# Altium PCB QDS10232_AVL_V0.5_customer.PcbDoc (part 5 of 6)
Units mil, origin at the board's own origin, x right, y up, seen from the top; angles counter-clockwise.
Board outline 3500 x 3799 mil, 6 copper layers (Top Layer, GND, INT1, PWR1, PWR2, Bottom Layer), stack 78.834 mil thick; 254 components, 204 nets, 7039 pads, 595 vias.
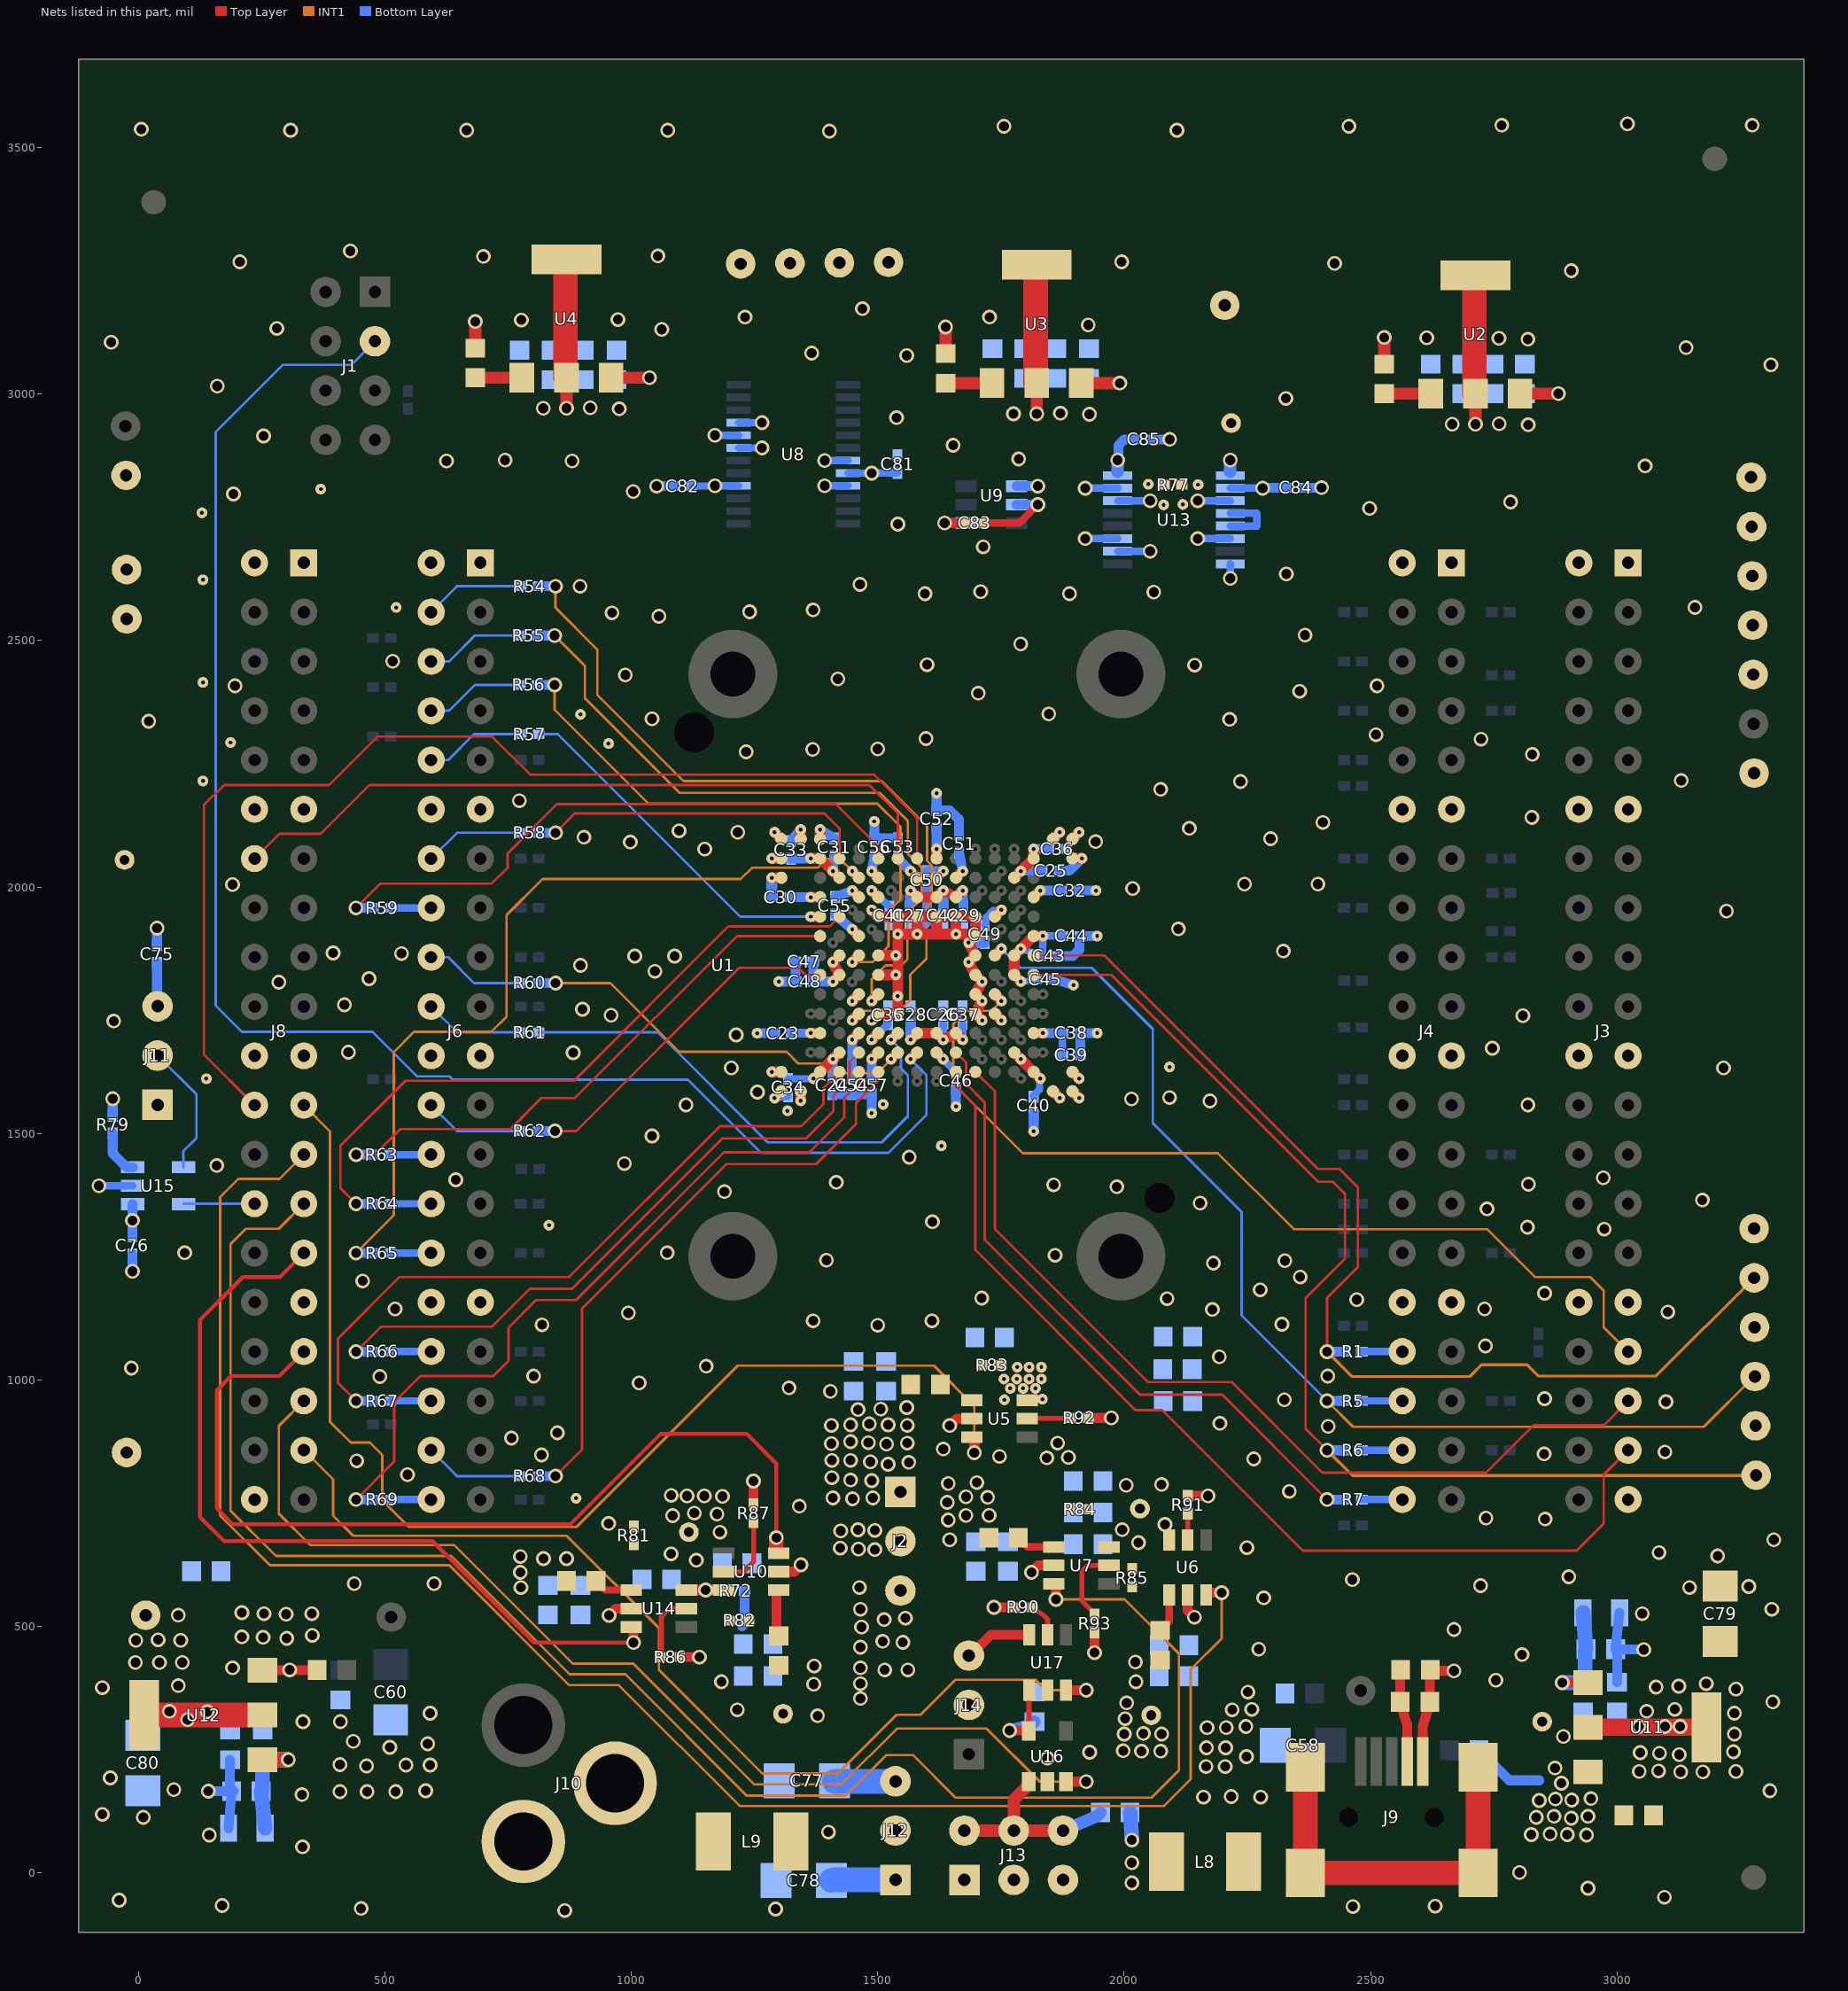
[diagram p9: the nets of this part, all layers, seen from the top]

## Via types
v1: diameter 30, hole 20, Top Layer to Bottom Layer, 595 vias

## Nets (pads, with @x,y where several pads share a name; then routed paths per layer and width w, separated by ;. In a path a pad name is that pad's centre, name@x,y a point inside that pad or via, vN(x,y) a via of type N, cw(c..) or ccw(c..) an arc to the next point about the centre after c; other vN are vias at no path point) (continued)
DQ16: pad.@1448.34,1729.46 R54.2 U1.E5 | length 1597.2
  Top Layer w22: pad.@1448.34,1729.46 U1.E5@1461.91,1743.02
  INT1 w5: v1(846.4,2610) 846.4,2566.6 931,2482 931,2390 1106,2215 1508,2215 1600,2123 1600,2053 1609,2044 1609,1969 1599,1959 1599,1855 1566,1822 1566,1770 1545,1749 1467.88,1749 pad.@1448.34,1729.46
  Bottom Layer w20: R54.2@812,2610 v1(846.4,2610)
DQ16_1: J6.4 R54.1 | length 203.8
  Bottom Layer w5: J6.4@593.96,2557.56 646.4,2610 R54.1@776,2610
DQ17: pad.@1487.71,1768.83 R55.2 U1.F6 | length 1401.7
  Top Layer w22: pad.@1487.71,1768.83 U1.F6@1501.28,1782.39
  INT1 w5: v1(844.4,2510) 906,2448.4 906,2383 1098,2191 1504,2191 1561,2134 1561,2068 1589,2040 1589,1977 1560,1948 1560,1853 1548,1841 1516,1841 1487.71,1812.71 pad.@1487.71,1768.83
  Bottom Layer w20: R55.2@810,2510 v1(844.4,2510)
DQ17_1: J6.6 R55.1 | length 203.8
  Bottom Layer w5: J6.6@593.96,2457.56 630.36,2457.56 682.8,2510 R55.1@776,2510
DQ18: pad.@1448.34,1847.57 R56.2 U1.E8 | length 1243.1
  Top Layer w22: pad.@1448.34,1847.57 U1.E8@1461.91,1861.13
  INT1 w5: v1(844.4,2410) 844.4,2359.52 1034.92,2169 1499,2169 1546,2122 1546,1975 1522,1951 1522,1880 1489.57,1847.57 pad.@1448.34,1847.57
  Bottom Layer w20: R56.2@810,2410 v1(844.4,2410)
DQ18_1: J6.8 R56.1 | length 203.8
  Bottom Layer w5: J6.8@593.96,2357.56 630.36,2357.56 682.8,2410 R56.1@776,2410
DQ19: pad.@1363.98,1939.87 R57.2 U1.C10 | length 724.5
  Top Layer w22: pad.@1363.98,1939.87 U1.C10@1383.17,1939.87
  Bottom Layer w5: R57.2@812,2310 851,2310 1221.13,1939.87 pad.@1363.98,1939.87
DQ19_1: J6.10 R57.1 | length 203.8
  Bottom Layer w5: J6.10@593.96,2257.56 628.56,2257.56 681,2310 R57.1@776,2310
DQ20: R58.2 U1.D13 | length 699.8
  Top Layer w5: v1(846.4,2110) 885.4,2149 1392,2149 1422.54,2118.46 U1.D13@1422.54,2057.98
  Bottom Layer w20: R58.2@812,2110 v1(846.4,2110)
DQ20_1: J6.14 R58.1 | length 203.8
  Bottom Layer w5: J6.14@593.96,2057.56 646.4,2110 R58.1@776,2110
DQ21: R59.2 U1.F13 | length 1257.7
  Top Layer w5: v1(441.56,1957.56) 491,2007 717,2007 749,2039 749,2068 849,2168 1415,2168 1501.28,2081.72 U1.F13@1501.28,2057.98
  Bottom Layer w20: v1(441.56,1957.56) R59.2@475.96,1957.56
DQ21_1: J6.16 R59.1 | length 82
  Bottom Layer w15: R59.1@511.96,1957.56 J6.16@593.96,1957.56
DQ22: pad.@1527.08,1650.72 R60.2 U1.G3 | length 822
  Top Layer w22: pad.@1527.08,1650.72 U1.G3@1540.65,1664.28
  INT1 w5: v1(846.4,1805.12) 957.88,1805.12 1097,1666 1315,1666 1339,1642 1386,1642 1406,1622 1498.36,1622 pad.@1527.08,1650.72
  Bottom Layer w20: R60.2@812,1805.12 v1(846.4,1805.12)
DQ22_1: J6.18 R60.1 | length 203.8
  Bottom Layer w5: J6.18@593.96,1857.56 628.44,1857.56 680.88,1805.12 R60.1@776,1805.12
DQ23: pad.@1527.08,1690.09 R61.2 U1.G4 | length 1051.7
  Top Layer w22: pad.@1527.08,1690.09 U1.G4@1540.65,1703.65
  Bottom Layer w5: R61.2@812,1705.12 1053.88,1705.12 1277,1482 1508,1482 1561,1535 1561,1618 1547,1632 1547,1670.16 pad.@1527.08,1690.09
DQ23_1: J6.20 R61.1 | length 203.8
  Bottom Layer w5: J6.20@593.96,1757.56 646.4,1705.12 R61.1@776,1705.12
DQ24: R62.2 U1.C7 | length 715.2
  Top Layer w5: v1(845.36,1505.12) 888.12,1505.12 1219,1836 1338.53,1836 1352.76,1821.76 U1.C7@1383.17,1821.76
  Bottom Layer w20: R62.2@810.96,1505.12 R62.2@812,1505.12 v1(845.36,1505.12)
DQ24_1: J6.24 R62.1 | length 203.8
  Bottom Layer w5: J6.24@593.96,1557.56 646.4,1505.12 R62.1@776,1505.12
DQ25: R63.2 U1.C9 | length 1159.3
  Top Layer w5: v1(442,1457) 479.36,1457 531.36,1509 755,1509 818,1572 886,1572 1214.5,1900.5 U1.C9@1383.17,1900.5
  Bottom Layer w20: v1(442,1457) R63.2@475.36,1457 R63.2@476.4,1457
DQ25_1: J6.26 R63.1 | length 82
  Bottom Layer w15: R63.1@511.36,1457 J6.26@593.36,1457
DQ26: R64.2 U1.D10 | length 1370
  Top Layer w5: v1(441.56,1357.56) 410,1389.12 410,1475 542,1607 884,1607 1197,1920 1402.66,1920 U1.D10@1422.54,1939.87
  Bottom Layer w20: v1(441.56,1357.56) R64.2@475.96,1357.56
DQ26_1: J6.28 R64.1 | length 82
  Bottom Layer w15: R64.1@511.96,1357.56 J6.28@593.96,1357.56
DQ27: pad.@1448.34,2032.18 R65.2 U1.E12 | length 1716.4
  Top Layer w22: pad.@1448.34,2032.18 U1.E12@1461.91,2018.61
  INT1 w5: v1(441.56,1257.56) 518,1334 518,1665 559,1706 716,1706 747,1737 747,1943 820,2016 1222,2016 1245,2039 1378,2039 1396,2057 1423.52,2057 pad.@1448.34,2032.18
  Bottom Layer w20: v1(441.56,1257.56) R65.2@475.96,1257.56
DQ27_1: J6.30 R65.1 | length 82
  Bottom Layer w15: R65.1@511.96,1257.56 J6.30@593.96,1257.56
DQ28: R66.2 U1.E3 | length 1345.5
  Top Layer w5: v1(441.56,1057.56) 492,1108 717,1108 794,1185 880,1185 1185,1490 1355,1490 1410,1545 1410,1576 1443,1609 1443,1645.38 U1.E3@1461.91,1664.28
  Bottom Layer w20: v1(441.56,1057.56) R66.2@475.96,1057.56
DQ28_1: J6.34 R66.1 | length 82
  Bottom Layer w15: R66.1@511.96,1057.56 J6.34@593.96,1057.56
DQ29: R67.2 U1.D2 | length 1436.5
  Top Layer w5: v1(441.56,957.56) 405,994.12 405,1084 530,1209 874,1209 1180,1515 1345,1515 1390,1560 1390,1592.38 U1.D2@1422.54,1624.91
  Bottom Layer w20: v1(441.56,957.56) R67.2@475.96,957.56
DQ29_1: J6.36 R67.1 | length 82
  Bottom Layer w15: R67.1@511.96,957.56 J6.36@593.96,957.56
DQ30: R68.2 U1.F2 | length 1232.1
  Top Layer w5: v1(846.4,805.12) 900,858.72 900,1145 1193,1438 1375,1438 1456,1519 1456,1562 1501.28,1607.28 U1.F2@1501.28,1624.91
  Bottom Layer w20: R68.2@812,805.12 v1(846.4,805.12)
DQ30_1: J6.38 R68.1 | length 203.8
  Bottom Layer w5: J6.38@593.96,857.56 646.4,805.12 R68.1@776,805.12
DQ31: R69.2 U1.E2 | length 1559.9
  Top Layer w5: v1(441.56,757.56) 519,835 519,955 572,1008 720,1008 751,1039 751,1106 807,1162 888,1162 1188,1462 1361,1462 1432,1533 1432,1572 1461.91,1601.91 U1.E2@1461.91,1624.91
  Bottom Layer w20: v1(441.56,757.56) R69.2@475.96,757.56
DQ31_1: J6.40 R69.1 | length 82
  Bottom Layer w15: R69.1@511.96,757.56 J6.40@593.96,757.56
E1: J8.28 U15.5 | length 144.5
  Bottom Layer w5: U15.5@91.57,1356.6 92.54,1357.56 J8.28@235.69,1357.56
E#: E#.1 R1.2 U1.P8 | length 2235.4
  Top Layer w5: U1.P8@1816.24,1861.13 1959.87,1861.13 2393,1428 2437,1428 2474,1391 2474,1229 2411.64,1166.64 v1(2411.64,1057.56)
  INT1 w6: v1(2411.64,1057.56) 2462.2,1007 2701,1007 2725,1031 2817,1031 2840,1008 3079,1008 E#.1@3278,1207
  Bottom Layer w20: v1(2411.64,1057.56) R1.2@2446.04,1057.56
E#_1: J4.34 R1.1 | length 82
  Bottom Layer w15: R1.1@2482.04,1057.56 J4.34@2564.04,1057.56
EXT_VCCE_EN: J8.25 U6.3 | length 3523.1
  Top Layer w20: U6.3@2166,568.64 v1(2197.6,568.64)
  INT1 w5: J8.25@335.69,1457.56 286.13,1408 203,1408 166,1371 166,725 267,624 631,624 874,381 975,381 1220,136 2081,136 2135,190 2135,413 2197.6,475.6 v1(2197.6,568.64)
G#: G#.1 R6.2 U1.P7 | length 2307.8
  Top Layer w5: U1.P7@1816.24,1821.76 1974.24,1821.76 2394,1402 2423,1402 2448,1377 2448,1246 2368,1166 2368,901.2 v1(2411.64,857.56)
  INT1 w6: v1(2411.64,857.56) 2463.2,806 G#.1@3277,806
  Bottom Layer w20: v1(2411.64,857.56) R6.2@2446.04,857.56
G#_1: J4.38 R6.1 | length 82
  Bottom Layer w15: R6.1@2482.04,857.56 J4.38@2564.04,857.56
GND: C1.2 C2.2 C3.2 C4.2 C5.2 C6.2 C7.2 C8.2 C9.2 C10.2 C11.2 C12.2 C13.2 C14.2 C15.2 C16.2 C17.2 C18.2 C19.2 C20.2 C21.2 C22.2 C23.2 C24.2 C25.2 C26.2 C27.2 C28.2 C29.2 C30.2 C31.2 C32.2 C33.2 C34.2 C35.2 C36.2 C37.2 C38.2 C39.2 C40.2 C41.2 C42.2 C43.2 C44.2 C45.2 C46.2 C47.2 C48.2 C49.2 C50.2 C51.2 C52.2 C53.2 C54.2 C55.2 C56.2 C57.2 C58.2 C59.2 C62.2 C63.2 C64.2 C65.2 C66.2 C67.2 C68.2 C69.2 C70.2 C71.2 C72.2 C73.2 C74.2 C75.1 C76.1 C77.2 C78.2 C79.2 C80.2 C81.2 C82.2 C83.2 C84.2 C85.2 C86.2 C87.2 GND1.1 GND2.1 GND3.1 GND4.1 GND5.1 GND6.1 GND7.1 GND8.1 GND9.1 GND10.1 GND11.1 GND12.1 GND13.1 GND14.1 J3.11 J3.12 J3.21 J3.22 J3.31 J3.32 J3.39 J4.11 J4.12 J4.21 J4.22 J4.31 J4.32 J6.11 J6.12 J6.21 J6.22 J6.31 J6.32 J8.11 J8.12 J8.21 J8.22 J8.31 J9.5 J11.1 L8.1 L9.1 pad.@129,2759 pad.@131,2215 pad.@131,2415 pad.@131,2623 pad.@138,1611 pad.@187,2293 pad.@370,2807 pad.@523,2567 pad.@833,1314 pad.@888,760 pad.@897,2350 pad.@954,2291 pad.@1255.3,1703.45 pad.@1285.24,1624.91 pad.@1285.24,2018.61 pad.@1285.24,2057.98 pad.@1290.86,1571.98 pad.@1290.86,2110.92 pad.@1299.19,1808.2 pad.@1317,1546 pad.@1343.8,2116.54 pad.@1343.79,1566.36 pad.@1383.17,2116.54 pad.@1448.34,1768.83 pad.@1448.34,1914.07 pad.@1487.71,1540.94 pad.@1487.71,1729.46 pad.@1487.71,1953.44 pad.@1492.98,2133.05 pad.@1511,1559 pad.@1536.7,1821.76 pad.@1536.7,1861.13 pad.@1540.65,1778.45 pad.@1540.65,1904.45 pad.@1580.02,1904.45 pad.@1619.39,2190.09 pad.@1629,1475 pad.@1658.76,1554.51 pad.@1658.76,1904.45 pad.@1684.56,1847.57 pad.@1684.56,1886.94 pad.@1711.69,1729.46 pad.@1711.69,1768.83 pad.@1711.69,1808.2 pad.@1816.24,1504.36 pad.@1869.17,1571.98 pad.@1869.17,2110.92 pad.@1897,1801 pad.@1908.54,1571.98 pad.@1908.54,1611.35 pad.@1908.54,2110.92 pad.@1914.16,2057.98 pad.@1942.73,1992.81 pad.@1945.2,1703.65 pad.@1945.2,1900.5 pad.@2092,1635 R2.2 R3.2 R4.2 R71.2 R72.2 R74.2 R75.2 R78.1 R86.2 R87.2 R90.2 R91.2 R92.2 R93.2 U1.A1 U1.A2 U1.A12 U1.A13 U1.A14 U1.B1 U1.B14 U1.C14 U1.E6 U1.E9 U1.F5 U1.F7 U1.F8 U1.F10 U1.G5 U1.G10 U1.H10 U1.J10 U1.K10 U1.L5 U1.L6 U1.L7 U1.L8 U1.L9 U1.L10 U1.R1 U1.R14 U1.T1 U1.T2 U1.T13 U1.T14 U2.3 U3.3 U4.3 U5.2 U6.2 U7.2 U8.7 U8.8 U8.9 U8.19 U9.1 U9.2 U10.2 U13.6 U13.8 U13.11 U14.2 U15.2 U16.2 U17.2 | length 4934.4
  Top Layer w15: C83.2@1715,2738 1787.18,2738 v1(1824.78,2775.6)
  Top Layer w20: v1(954.82,522.4) 968.82,536.4 U14.2@1004.64,536.4 ; R86.2@1096.9,438 v1(1138.1,438) ; R87.2@1248,753.9 v1(1248,795.1) ; U10.2@1294.45,611.2 1330.27,611.2 v1(1344.27,625.2) ; v1(1646.13,907.6) 1660.13,921.6 U5.2@1695.94,921.6 ; v1(1735.9,539) R90.2@1777.1,539 ; v1(1812,610) 1826,624 U7.2@1861.82,624 ; R92.2@1932.9,923 v1(1974.1,923) ; v1(1940,446.9) R93.2@1940,488.1 ; U6.2@2128.6,568.64 2128.6,532.82 v1(2142.6,518.82) ; R91.2@2128.9,765 v1(2170.1,765) ; J9.5@2605.61,226.39 2605.61,296.61 C62.2@2620,347 R78.1@2620,411 ; R78.1@2621,410 v1(2669,410)
  Top Layer w22: pad.@1285.24,1624.91 U1.A2@1304.42,1624.91 ; pad.@1285.24,2018.61 U1.A12@1304.42,2018.61 ; pad.@1285.24,2057.98 U1.A13@1304.42,2057.98 ; pad.@1290.86,1571.98 U1.A1@1304.42,1585.54 ; pad.@1290.86,2110.92 U1.A14@1304.42,2097.35 ; pad.@1343.79,1566.36 U1.B1@1343.8,1585.54 ; U1.B14@1343.8,2097.35 pad.@1343.8,2116.54 ; U1.C14@1383.17,2097.35 pad.@1383.17,2116.54 ; pad.@1448.34,1768.83 U1.E6@1461.91,1782.39 ; pad.@1448.34,1914.07 U1.E9@1461.91,1900.5 ; pad.@1487.71,1729.46 U1.F5@1501.28,1743.02 U1.G5@1540.65,1743.02 pad.@1540.65,1778.45 pad.@1540.65,1813.87 ; pad.@1487.71,1953.44 U1.F10@1501.28,1939.87 U1.G10@1540.65,1939.87 ; U1.F7@1501.28,1821.76 pad.@1536.7,1821.76 ; U1.F8@1501.28,1861.13 pad.@1536.7,1861.13 ; 1540.65,1798.17 1540.65,1833.6 1540.65,1869.02 pad.@1540.65,1904.45 ; 1619.39,1904.45 U1.J10@1619.39,1939.87 ; pad.@1650.87,1904.45 1615.44,1904.45 pad.@1580.02,1904.45 ; U1.L9@1694.18,1904.45 pad.@1658.76,1904.45 U1.K10@1658.76,1939.87 ; pad.@1711.69,1729.46 U1.L5@1698.13,1743.02 pad.@1711.69,1768.83 U1.L6@1698.13,1782.39 pad.@1711.69,1808.2 U1.L7@1698.13,1821.76 pad.@1684.56,1847.57 U1.L8@1698.13,1861.13 pad.@1684.56,1886.94 U1.L9@1698.13,1900.5 U1.L10@1698.13,1939.87 U1.K10@1658.76,1939.87 ; U1.R1@1855.61,1585.54 pad.@1869.17,1571.98 ; U1.R14@1855.61,2097.35 pad.@1869.17,2110.92 ; U1.T1@1894.98,1585.54 pad.@1908.54,1571.98 ; U1.T2@1894.98,1624.91 pad.@1908.54,1611.35 ; U1.T13@1894.98,2057.98 pad.@1914.16,2057.98 ; U1.T14@1894.98,2097.35 pad.@1908.54,2110.92 ; pad.@1540.65,1904.45 pad.@1580.02,1904.45 ; pad.@1540.65,1904.45 U1.G10@1540.65,1939.87 ; U1.G10@1540.65,1939.87 U1.H10@1580.02,1939.87 ; pad.@1580.02,1904.45 U1.H10@1580.02,1939.87 ; U1.H10@1580.02,1939.87 U1.J10@1619.39,1939.87 ; U1.J10@1619.39,1939.87 U1.K10@1658.76,1939.87
  Top Layer w25: R4.2@683.7,3093 v1(683.7,3146.93) ; U4.3@959.07,3033 v1(1037,3033) ; R3.2@1637.7,3082 v1(1637.7,3135.93) ; U3.3@1913.07,3022 v1(1991,3022) ; R2.2@2527.7,3060.71 v1(2527.7,3114.64) ; U2.3@2803.07,3000.71 v1(2881,3000.71)
  Bottom Layer w15: v1(-80,1394) U15.2@-11.57,1394 ; v1(1169.84,2916.13) U8.8@1217.56,2916.13 ; U8.7@1217.56,2890.54 v1(1265.28,2890.54) ; U8.9@1217.56,2941.72 v1(1265.28,2941.72) ; pad.@1290.86,1571.98 C34.2@1318,1575 ; v1(1392.28,2864.95) U8.19@1440,2864.95 ; v1(1921,2706.61) U13.11@1986.83,2706.61 ; v1(2149.35,2706.61) U13.6@2215.17,2706.61 ; v1(2215.17,2626) U13.8@2215.17,2655.43
  Bottom Layer w20: v1(-12,1220.6) C76.1@-12,1255 ; C75.1@38,1882 v1(38,1916.4) ; v1(141.9,166) R75.2@183.1,166 ; C74.2@183,91 R75.2@189,166 ; C73.2@186,230 186,174 R75.2@194,166 ; v1(1051.6,2813) C82.2@1086,2813 ; 1224.78,500.4 1229.82,505.44 R72.2@1229.82,572.4 ; pad.@1255.3,1703.45 C23.2@1289.7,1703.45 ; pad.@1299.19,1808.2 C48.2@1333.59,1808.2 1333.59,1849 C47.2@1333,1849 ; C33.2@1324,2093 pad.@1343.8,2116.54 ; pad.@1383.17,2116.54 C31.2@1411.7,2098.45 ; C24.2@1407.71,1580 C54.2@1447.71,1580 C57.2@1487.71,1580 ; C55.2@1413,1943.99 pad.@1448.34,1914.07 ; pad.@1487.71,1540.94 C57.2@1487.71,1575.34 ; pad.@1492.98,2133.05 C56.2@1492.98,2098.65 1540.31,2098.65 C53.2@1540.65,2098.98 ; 1597,1926 1600,1929 C50.2@1600,1996 ; pad.@1619.39,2190.09 C52.2@1619.39,2155.69 1646.31,2155.69 1665,2137 C51.2@1665,2106 ; pad.@1658.76,1554.51 C46.2@1658.76,1588.91 ; pad.@1685,1886 C49.2@1717,1886 ; U9.2@1781.36,2775.6 v1(1824.78,2775.6) ; U9.1@1781.36,2813 v1(1824.78,2813) ; pad.@1816.24,1504.36 C40.2@1816.24,1538.76 ; C45.2@1858,1813 pad.@1897,1801 ; C43.2@1866,1860 1896,1860 1909,1873 1909,1898.7 C44.2@1910.8,1900.5 pad.@1945.2,1900.5 ; C25.2@1869,2033 1889.18,2033 pad.@1914.16,2057.98 ; C32.2@1908.32,1992.81 pad.@1942.73,1992.81 ; C38.2@1910.8,1703.65 C38.2@1911,1703.65 ; C39.2@1911,1659 C38.2@1911,1703.65 ; pad.@1945.2,1703.65 C38.2@1911,1703.65 ; C85.2@2058,2908 v1(2092.4,2908) ; C84.2@2366,2810 v1(2400.4,2810) ; C71.2@3000,387 R74.2@3000,451 ; C72.2@3005,528 R74.2@2997,454 R74.2@3000,451 ; v1(3054,453) 3053.5,453.5 3002.5,453.5 R74.2@3000,451
  Bottom Layer w22: C30.2@1285.24,1981.76 pad.@1285.24,2018.61
  Bottom Layer w30: C87.2@2012,123 v1(2015.55,66.8)
  other v1: 865,-76 1293,-73 452,-72 2464,-68 2631,-67 170,-66 -39,-55 3096,-49 2941,-31 2015.55,-20.2 2802,1 2015.55,20.8 333,53 144,77 1400,83 10,113 -73,119 2161,154 2277,154 2217,155 332,159 3310,167 72,169 -57,193 2166,216 2205,216 1844,233 2248,236 1930,245 2167,254 2206,254 2168,295 2207,295 2247,297 334,307 1215,331 2219,331 2259,332 3316,347 2251,367 -73,376 1183,388 2754,391 2807,443 2273,454 2669,494 3051,526 3314,535 2283,558 3147,579 3267,581 2723,583 438,587 600,587 2463,595 2902,601 3204,643 3085,650 2249,660 3318,676 954,709 2854,718 2734,720 1341,744 2335,774 546,808 443,836 2263,840 1843,842 1887,843 1747,845 818,848 2852,850 3097,854 1633,860 1865,872 757,882 850,893 2414,906 2194,912 3099,956 2325,960 2853,962 1320,984 1016,994 490,1007 802,1008 2413,1008 -14,1024 1152,1028 2193,1047 2733,1069 1500,1111 819,1112 2320,1113 1369,1120 1610,1120 994,1136 3103,1138 2179,1143 521,1144 2731,1144 2472,1163 2087,1165 1711,1166 2853,1176 2276,1183 455,1201 2357,1209 2181,1237 2326,1242 1396,1243 1860,1253 94,1258 1073,1258 2974,1306 2818,1310 1611,1321 2736,1347 2154,1359 3173,1365 1189,1382 1985,1392 1857,1396 2820,1397 1416,1401 644,1406 2972,1410 159,1435 986,1439 1564,1452 1042,1495 1111,1558 2819,1558 2174,1566 2015,1570 2092,1573 1256,1584 1203,1633 3216,1633 882,1664 426,1665 2747,1673 1213,1700 -50,1728 2809,1739 959,1740 901,1752 418,1761 285,1807 468,1814 1048,1829 897,1841 1007,1860 1088,1860 534,1865 395,1866 2323,1870 2110,1915 3222,1951 2017,1997 191,2005 2244,2006 2393,2006 1149,2077 998,2091 1942,2092 2297,2098 904,2101 1216,2111 1097,2114 2132,2119 2403,2131 2827,2141 773,2175 2074,2198 2236,2214 3130,2216 2828,2269 1233,2274 1368,2279 1500,2280 2724,2300 1598,2301 2511,2309 21,2336 2214,2340 1042,2341 1847,2351 1704,2393 2356,2397 196,2408 2513,2408 1419,2422 988,2430 2143,2450 1600,2451 516,2458 1790,2493 2367,2511 1056,2549 961,2556 1240,2558 1369,2562 3158,2567 1596,2595 1889,2595 2060,2598 1709,2599 896,2610 1464,2614 2329,2635 1714,2690 1541,2736 2498,2768 2784,2781 193,2797 1004,2802 3057,2854 625,2864 880,2864 744,2866 1786,2868 1653,2896 254,2915 1538,2952 2328,2991 160,3016 3312,3059 1559,3078 1366,3083 3140,3094 -55,3105 2819,3111 2760.18,3113 2614,3114 1062,3131 281,3133 1927,3140 777,3150 973,3151 1231,3156 1727,3156 1469,3173 2907,3250 2427,3265 206,3268 1995,3268 700,3279 1054,3280 430,3290 1402,3533 309,3535 666,3535 1074,3535 2107,3535 6,3537 1756,3543 2456,3543 2766,3545 3274,3545 3021,3548
GND_EXT: C60.2 C61.2 J10.GND J10.GNDBREAK L9.2
  other v1: 409,165 464,165 522,165 583,167 463,217 543,219 592,219 409,220 510,255 587,262 436,267 410,307 592,324
INT#: J8.14 U1.G13 | length 1482.1
  Top Layer w5: J8.14@235.69,2057.56 286.13,2108 370,2108 469,2207 1483,2207 1540.65,2149.35 U1.G13@1540.65,2057.98
INT_VCCE_EN: J8.23 U5.3 | length 2409.2
  Top Layer w20: v1(1695.94,852.6) U5.3@1695.94,884.2
  INT1 w5: J8.23@335.69,1557.56 389,1504.25 389,915 431,873 470,873 495,848 495,756 549,702 889,702 1216,1029 1614,1029 1695.94,947.06 v1(1695.94,852.6)
NetC62_1: C62.1 J9.4 R78.2 | length 188.1
  Top Layer w20: R78.2@2561,412 2560,411 C62.1@2560,347 2574.11,300.89 J9.4@2574.11,226.39
NetC72_1: C72.1 R73.2 R74.1 U11.1 | length 237.1
  Top Layer w20: v1(2888.9,386.1) U11.1@2941,386.1
  Bottom Layer w20: R74.1@2937,454 R74.1@2941,450
  Bottom Layer w30: v1(2888.9,386.1) R73.2@2930.1,386.1 ; C72.1@2931,528 R74.1@2937,454 ; R73.2@2935,386.1 R74.1@2935,450
NetC74_1: C74.1 R75.1 R76.2 U12.1 | length 233.9
  Top Layer w30: U12.1@252,229.9 v1(304.1,229.9)
  Bottom Layer w20: R75.1@249,166 R75.1@252,169
  Bottom Layer w30: R75.1@249,166 C74.1@257,91 ; R75.1@252,169 R76.2@252,229.9 ; R76.2@262.9,229.9 v1(304.1,229.9)
NetC86_1: C86.1 U16.5 U17.1 | length 178.9
  Top Layer w10: U16.5@1806.6,288 1806.9,288.3 1806.9,289 1806.9,370.7 U17.1@1807.2,371
  Top Layer w20: v1(1767.5,289) 1806.9,289 U16.5@1808.7,289
  Bottom Layer w25: v1(1767.5,289) 1810.5,300.5 C86.1@1818,307
NetC87_1: C87.1 J13.4 J13.5 J13.6 U16.1 | length 399.4
  Top Layer w25: J13.4@1676,86 J13.5@1776,86 ; U16.1@1805.1,183.71 U16.1@1806.6,185.21 1806.6,179.71 1776,149.11 J13.5@1776,86 ; J13.6@1876,86 J13.5@1776,86
  Bottom Layer w25: J13.6@1876,86 1945.5,115.5 C87.1@1952,123
NetJ9_6: J9.6 J9.7 J9.8 J9.9 L8.2 | length 799.9
  Top Layer w50: J9.8@2353.05,17 J9.8@2367.42,2.63 ; J9.6@2367.42,214.57 2367.42,133 J9.8@2367.42,2.63 ; J9.7@2717.81,214.57 J9.9@2717.81,0.01 J9.8@2367.42,0.01 J9.8@2367.42,2.63
NetJ11_2: J11.2 U15.4 | length 270.3
  Bottom Layer w5: J11.2@39,1658 118,1579 118,1491 91.57,1464.57 U15.4@91.57,1431.4
NetJ14_3: J14.3 U17.6 | length 139.6
  Top Layer w20: J14.3@1685,441 1687.27,441 1729.27,483 U17.6@1807.2,483
NetL1_2: L1.2 R83.2 U5.1
NetL2_1: L2.1 R85.1 U6.1 | length 84.2
  Top Layer w15: L2.1@2073,492 2091.2,510.2 U6.1@2091.2,568.64
NetL3_2: L3.2 R84.2 U7.1 | length 83.9
  Top Layer w15: L3.2@1785.59,680 1804.19,661.4 U7.1@1861.82,661.4
NetL4_2: L4.2 R81.2 U14.1 | length 83.9
  Top Layer w15: L4.2@928.41,592.4 947.01,573.8 U14.1@1004.64,573.8
NetL5_1: L5.1 R82.1 U10.1 | length 74.6
  Top Layer w15: L5.1@1294.45,499.77 L5.1@1294.82,499.4
  Top Layer w20: L5.1@1294.45,499.77 U10.1@1294.45,573.8
NetL6_2: L6.2 L7.2 R88.1 R89.1 U11.3 U12.3 | length 249.3
  Top Layer w20: U12.3@252,411 L7.2@354,411
  Bottom Layer w20: L6.2@2720,249 2781,188 2842,188
  other v1: 2938,77 2826,78 2899,78 2864,79 2907,111 2836,113 2872,115 2941,115 2842,147 2908,148 2875,150 2947,151 2887,182 2874,213 307,412 191,416 301,476 253,478 210,479 353,482 300,525 255,526 352,526 210,528
NetR2_1: R2.1 U2.1 | length 94.3
  Top Layer w25: R2.1@2527.7,3000.71 U2.1@2621.97,3000.71
NetR3_1: R3.1 U3.1 | length 94.3
  Top Layer w25: R3.1@1637.7,3022 U3.1@1731.97,3022
NetR4_1: R4.1 U4.1 | length 94.3
  Top Layer w25: R4.1@683.7,3033 U4.1@777.97,3033
NetR79_2: R79.2 U15.3 | length 92.3
  Bottom Layer w20: R79.2@-52,1500 -52,1460.02 -23.39,1431.4 U15.3@-11.57,1431.4
NetR86_1: R86.1 U14.5 | length 141.6
  Top Layer w10: R86.1@1061,436 1061,520 1077.4,536.4 U14.5@1111.82,536.4
NetR87_1: R87.1 U10.5 | length 149.6
  Top Layer w10: U10.5@1187.27,611.2 1227.62,611.2 1248,631.58 R87.1@1248,712
NetR90_1: R90.1 U17.5 | length 71.6
  Top Layer w10: R90.1@1813,539 1820,534 1836.63,522.37 1844.6,514.4 U17.5@1844.6,483
NetR91_1: R91.1 U6.5 | length 53.3
  Top Layer w10: U6.5@2128.6,675.82 2128.8,676.02 2128.8,728.8 R91.1@2129,729
NetR92_1: R92.1 U5.5 | length 88.5
  Top Layer w10: U5.5@1803.13,921.6 1803.83,922.3 1890.3,922.3 R92.1@1891,923
NetR93_1: R93.1 U7.5 | length 158.7
  Top Layer w10: R93.1@1940,524 1940,526 1914,552 1914,612 1926,624 U7.5@1969,624
NetU13_4: U13.4 U13.5 | length 133.2
  Bottom Layer w15: U13.5@2215.17,2732.2 2269,2732.2 2269,2757.8 U13.4@2215.17,2757.8
PG#: R7.2 U1.K3 | length 1350.9
  Top Layer w5: U1.K3@1658.76,1664.28 1679,1644.04 1679,1601 1717.03,1562.97 1717.03,1284.97 2032,970 2199.2,970 v1(2411.64,757.56)
  Bottom Layer w20: v1(2411.64,757.56) R7.2@2446.04,757.56
PG#_1: J4.40 R7.1 | length 82
  Bottom Layer w15: R7.1@2482.04,757.56 J4.40@2564.04,757.56
RESMIO: J1.2 pad.@1566.45,1650.72 U1.H3 | length 3305.9
  Top Layer w22: pad.@1566.45,1650.72 U1.H3@1580.02,1664.28
  Bottom Layer w5: J1.2@480,3107 432,3059 293,3059 157,2923 157,1759 210,1706 475,1706 565,1616 631,1616 638,1609 1115,1609 1263,1461 1522,1461 1599,1538 1599,1618.16 pad.@1566.45,1650.72
TID_CLK: J3.37 U1.K2 | length 2096.6
  Top Layer w5: U1.K2@1658.76,1624.91 1658.76,1596.24 1698.13,1556.87 1698.13,1263.87 2023,939 2077,939 2362,654 2918,654 2972.75,708.75 2972.75,808 J3.37@3022.31,857.56
TID_IN: J3.35 U1.L2 | length 1884.7
  Top Layer w5: U1.L2@1698.13,1624.91 1737.5,1585.54 1737.5,1306.5 2048,996 2218,996 2402,812 2734,812 2830.25,908.25 2973,908.25 J3.35@3022.31,957.56
TM: J8.24 U1.H13 | length 2305.9
  Top Layer w5: J8.24@235.69,1557.56 133,1660.25 133,2166 174,2207 387,2207 485,2305 718,2305 795,2228 1492,2228 1580.02,2139.98 U1.H13@1580.02,2057.98
TM_CLK: J3.33 pad.@1751.06,1768.83 U1.M6 | length 1895.5
  Top Layer w22: U1.M6@1737.5,1782.39 pad.@1751.06,1768.83
  INT1 w5: pad.@1751.06,1768.83 1731.24,1749 1680,1749 1653,1722 1653,1601 1794,1460 2190,1460 2344,1306 2736,1306 2833,1209 2945,1209 2972.87,1181.13 2972.87,1107 J3.33@3022.31,1057.56
VCC: C23.1 C24.1 C25.1 C26.1 C27.1 C28.1 C29.1 C30.1 C31.1 C32.1 C33.1 C34.1 C35.1 C36.1 C37.1 C38.1 C39.1 C40.1 C41.1 C42.1 C84.1 pad.@1363.98,1703.65 pad.@1363.98,1979.24 pad.@1363.98,2057.98 pad.@1369.6,1611.35 pad.@1408.97,1650.72 pad.@1408.97,2032.18 pad.@1487.71,1690.09 pad.@1487.71,1992.81 pad.@1566.45,1690.09 pad.@1566.45,1992.81 pad.@1632.95,1690.09 pad.@1632.95,1992.81 pad.@1672.32,1690.09 pad.@1672.32,1992.81 pad.@1790.43,1650.72 pad.@1790.43,2032.18 pad.@1816.24,2077.17 pad.@1829.8,1611.35 pad.@1829.8,1992.81 pad.@1835.42,1703.65 pad.@2119,2776 pad.@2150,2816 R77.2 U1.C2 U1.C4 U1.C11 U1.C13 U1.D3 U1.D12 U1.F4 U1.F11 U1.H4 U1.H11 U1.J4 U1.J11 U1.K4 U1.K11 U1.N3 U1.N12 U1.P2 U1.P4 U1.P11 U1.P13 U13.1 U13.2 U13.3 VCC.1 | length 1636.5
  Top Layer w20: pad.@1632.95,1992.81 U1.K11@1658.76,1979.24
  Top Layer w22: pad.@1363.98,1703.65 U1.C4@1383.17,1703.65 ; pad.@1363.98,1979.24 U1.C11@1383.17,1979.24 ; pad.@1363.98,2057.98 U1.C13@1383.17,2057.98 pad.@1408.21,2032.93 ; pad.@1369.6,1611.35 U1.C2@1383.17,1624.91 pad.@1408.97,1650.72 U1.D3@1422.54,1664.28 ; pad.@1408.97,2032.18 U1.D12@1422.54,2018.61 ; pad.@1487.71,1690.09 U1.F4@1501.28,1703.65 ; pad.@1487.71,1992.81 U1.F11@1501.28,1979.24 ; pad.@1566.45,1690.09 U1.H4@1580.02,1703.65 U1.J4@1619.39,1703.65 pad.@1632.95,1690.09 U1.K4@1658.76,1703.65 pad.@1672.32,1690.09 ; pad.@1566.45,1992.81 U1.H11@1580.02,1979.24 ; U1.H11@1583.96,1979.24 U1.J11@1619.39,1979.24 pad.@1632.95,1992.81 ; U1.K11@1658.76,1979.24 pad.@1672.32,1992.81 ; U1.N3@1776.87,1664.28 pad.@1790.43,1650.72 U1.P2@1815.48,1625.67 ; U1.N12@1776.87,2018.61 pad.@1790.43,2032.18 U1.P13@1815.48,2057.23 ; U1.P2@1816.24,1624.91 pad.@1829.8,1611.35 ; U1.P4@1816.24,1703.65 pad.@1835.42,1703.65 ; U1.P11@1816.24,1979.24 pad.@1829.8,1992.81 ; U1.P13@1816.24,2057.98 pad.@1816.24,2077.17
  Bottom Layer w15: C34.1@1318,1611 1369.6,1611 pad.@1369.6,1611.35 ; pad.@1487.71,1690.09 C35.1@1521,1722 ; pad.@1487.71,1992.81 C41.1@1524,1960 ; pad.@1632.95,1690.09 C26.1@1632.95,1722.45 ; pad.@1672.32,1690.09 C37.1@1672.32,1722.45 ; pad.@1790.43,1650.72 pad.@1792.33,1650.72 ; C40.1@1816.24,1574.76 1816.24,1576.76 1828.46,1588.99 1828.46,1610.01 pad.@1829.8,1611.35 ; C39.1@1874,1659 C39.1@1875,1659 1874.9,1659.1 1874.9,1703.55 C38.1@1874.8,1703.65 ; v1(2149.35,2783.39) U13.3@2215.17,2783.39 ; U13.2@2215.17,2808.98 v1(2281,2808.98)
  Bottom Layer w18: C23.1@1324.6,1703.65 pad.@1363.98,1703.65
  Bottom Layer w20: C30.1@1322.5,1979.24 pad.@1363.98,1979.24 ; C33.1@1324,2057 1324.98,2057.98 pad.@1363.98,2057.98 ; C24.1@1407.71,1616 pad.@1408.97,1650.72 ; pad.@1408.97,2032.18 C31.1@1411.7,2062.45 ; C27.1@1564,1960 pad.@1566.45,1992.81 ; pad.@1566.45,1690.09 C28.1@1566.45,1722.45 ; C42.1@1633,1960 pad.@1632.95,1992.81 ; pad.@1672.32,1992.81 C29.1@1674,1960 ; pad.@1790.43,2032.18 C25.1@1831.74,2033.22 ; pad.@1816.24,2077.17 C36.1@1845.83,2077.17 ; pad.@1829.8,1992.81 C32.1@1872.32,1992.81 ; pad.@1835.42,1703.65 C38.1@1874.8,1703.65 ; v1(2281,2808.98) 2282.02,2810 C84.1@2330,2810
  Bottom Layer w25: U13.1@2215.17,2841.83 v1(2215.17,2866)
VCC_M: C15.1 C16.1 C17.1 C22.1 C63.1 C64.1 C75.2 C76.2 C81.1 C82.1 C83.1 C85.1 J2.2 J11.3 J13.1 pad.@1756,1002 pad.@1757,960 pad.@1769,983 pad.@1782,1002 pad.@1783,1026 pad.@1795,983 pad.@1807,1002 pad.@1807,1026 pad.@1820,983 pad.@1832,1002 pad.@1832,1026 pad.@1834,961 pad.@2049,2817 pad.@2080,2775 R71.1 R77.1 R79.1 R83.1 R84.1 R85.2 U5.6 U6.6 U7.6 U8.4 U8.20 U8.21 U9.4 U13.10 U13.14 U13.15 U13.16 U15.1 VCC1.1 VCC_M.1 | length 810.9
  Top Layer w15: v1@2052.65,2783 v1(2052.65,2783.39)
  Top Layer w20: v1(1635.58,2738.2) 1635.78,2738 C83.1@1679,2738
  Bottom Layer w15: C82.1@1122,2813 1122.39,2813.39 1169.46,2813.39 v1(1169.84,2813.77) U8.4@1217.56,2813.77 ; v1(1392.28,2813.77) U8.21@1440,2813.77 ; U8.20@1440,2839.36 v1(1487.72,2839.36) 1488.04,2839.68 1539.68,2839.68 C81.1@1540,2840 ; v1(1921,2808.98) U13.15@1986.83,2808.98 ; U13.10@1986.83,2681.02 v1(2052.65,2681.02) ; U13.14@1986.83,2783.39 v1(2052.65,2783.39)
  Bottom Layer w20: R79.1@-52,1536 v1(-52,1570.4) ; C76.2@-12,1291 -12,1356.17 U15.1@-11.57,1356.6 ; C75.2@38,1846 38,1759 J11.3@39,1758 ; v1(1635.58,2738.2) U9.4@1679,2738.2 ; v1(1986.83,2866) 1988.28,2867.46 1988.28,2896.28 2000,2908 C85.1@2022,2908
  Bottom Layer w25: U13.16@1986.83,2841.83 v1(1986.83,2866)
  other v1: 1494,656 1461,657 1424,659 2029,670 1425,694 1494,695 1460,696 1996,696.35 2082.82,707 2004,786.35 2075.82,788 -12,1323.59
VCC_REG: C20.1 C21.1 C71.1 C79.1 L3.1 R73.1 R88.2 U11.2 U11.4 VCCE_REG.1 | length 240
  Top Layer w35: U11.2@2941,295.55 U11.4@3181,295.55
  other v1: 3129,205 3174,205 3045,206 3241,206 3084,207 3126,240 3086,243 3047,244 3236,246 2891,277 3238,282 3044,297 3097,297 3128,297 3238,324 3060,328 3117,332 3241,373 3079,377 3125,379 3181,384 1646,676 1643,716 1679,725.35 1726,725.35 1641,752 1723,762 1679,763 1643,790 1701,792
VCC_REG_EN: J8.27 U7.3 | length 3542.6
  Top Layer w20: v1(1861.82,555) U7.3@1861.82,586.6
  INT1 w5: J8.27@335.69,1357.56 285,1306.87 217.87,1306.87 187,1276 187,735 279,643 635,643 875,403 988,403 1234,157 1435,157 1517,239 1572,239 1658,153 2056,153 2111,208 2111,445 2001,555 v1(1861.82,555)
VCCEXT: C18.1 C19.1 C77.1 J2.3 J12.3 L2.2 VCCEXT.1 | length 117.4
  Bottom Layer w50: C77.1@1412.6,185.95 J12.3@1530,185.95
  other v1: 2035,247 2074,247 1998,248 2000,282 2076,282 2039,283 2002,313 2005,345 1465,354 1465,384 2023.82,388 1514.13,411.94 1561.13,411.94 1465,416 2022.82,428 1465,458 1551,468 1510,470 1467,499 1513,514 1556,517 1465,535 1463,579
VCCIO: C13.1 C14.1 C67.1 C68.1 C78.1 J2.1 J3.1 J3.2 J4.1 J4.2 J6.1 J6.2 J8.1 J8.2 J8.40 J12.1 J13.2 L1.1 L5.2 VCCEXT1.1 | length 130
  Bottom Layer w50: C78.1@1406.1,-15 1412.6,-14.05 1530,-14.05 J12.1@1536,-14
  other v1: 1378,319 1370,383 1371,420 1449,759 1409,761 1490,761 1488,796 1445,797 1407,802 1521,829 1563,833 1485,834 1407,837 1445,837 1518,870 1406,871 1560,872 1481,873 1445,875 1406,908 1560,908 1445,909 1521,909 1483,911 1460,940 1506,941 1559,944 1404,977
VCCIO_REG: C65.1 C66.1 C73.1 C80.1 J12.2 J13.3 L4.1 R76.1 R89.2 U12.2 U12.4 VCCIO_REG.1 | length 240
  Top Layer w50: U12.4@12,320.45 U12.2@252,320.45
  other v1: 100,311 140,327 63,328 81,380 -6,427 43,427 89,427 -5,472 86,472 40,473 81,523 776,579 775,610 821.82,637.75 868.82,637.75 775,642
VCCIO_REG_EN: J8.29 U14.3 | length 1683.5
  Top Layer w8: J8.29@335.69,1257.56 287.13,1209 212,1209 125,1122 125,722 174,673 597,673 802.6,467.4 v1(1004.64,467.4)
  Top Layer w20: v1(1004.64,467.4) U14.3@1004.64,499
VCCIO_VCCEXT_EN: J8.33 U10.3 | length 1877.4
  Top Layer w8: J8.33@335.69,1057.56 286.13,1008 188,1008 159,979 159,740 192,707 876,707 1060,891 1234,891 1294.45,830.55 v1(1294.45,680.2)
  Top Layer w30: U10.3@1294.45,651.8 v1(1294.45,680.2)
VCCQ: C43.1 C44.1 C45.1 C46.1 C47.1 C48.1 C49.1 C50.1 C54.1 C55.1 C56.1 C57.1 C69.1 C70.1 pad.@1408.97,1808.2 pad.@1408.97,1847.57 pad.@1448.34,1690.09 pad.@1448.34,1992.81 pad.@1487.71,1650.72 pad.@1487.71,2032.18 pad.@1632.95,1650.72 pad.@1632.95,2032.18 pad.@1751.06,1729.46 pad.@1751.06,1953.44 pad.@1790.43,1808.2 pad.@1790.43,1874.7 pad.@1835.42,1900.5 R72.1 R81.1 R82.2 U1.D7 U1.D8 U1.E4 U1.E11 U1.F3 U1.F12 U1.J3 U1.J12 U1.M5 U1.M10 U1.N7 U1.N8 U1.P9 U10.6 U14.6 VCCQ1.1 VCCQ.1 | length 976.3
  Top Layer w22: U14.6@1107,573.8 U10.6@1192.09,573.8 ; pad.@1408.97,1808.2 U1.D7@1422.54,1821.76 pad.@1408.97,1847.57 U1.D8@1422.54,1861.13 ; pad.@1448.34,1690.09 U1.E4@1461.91,1703.65 ; pad.@1448.34,1992.81 U1.E11@1461.91,1979.24 ; pad.@1487.71,1650.72 U1.F3@1501.28,1664.28 ; pad.@1487.71,2032.18 U1.F12@1501.28,2018.61 ; U1.J3@1619.39,1664.28 pad.@1632.95,1650.72 ; U1.J12@1619.39,2018.61 pad.@1632.95,2032.18 ; U1.M5@1737.5,1743.02 pad.@1751.06,1729.46 ; U1.M10@1737.5,1939.87 pad.@1751.06,1953.44 ; U1.N8@1776.87,1857.19 U1.N7@1776.87,1821.76 pad.@1790.43,1808.2 ; U1.N8@1776.87,1861.13 pad.@1790.43,1874.7 U1.P9@1815.48,1899.75 ; U1.P9@1816.24,1900.5 pad.@1835.42,1900.5
  Bottom Layer w15: pad.@1632.95,1650.72 C46.1@1658.76,1624.91 C46.1@1656.26,1629.41 ; C49.1@1717,1924 1719.5,1926.5 1719.5,1937.5 1734.1,1952.1 1749.72,1952.1 pad.@1751.06,1953.44 ; pad.@1790.43,1808.2 1817.5,1810.5 C45.1@1822,1813 ; pad.@1790.43,1874.7 1825.5,1862.5 C43.1@1830,1860 1834.5,1862.5 pad.@1835.42,1900.5 C44.1@1874.8,1900.5
  Bottom Layer w20: C48.1@1369,1808.2 C47.1@1369,1849 ; C48.1@1369.59,1808.2 pad.@1408.97,1808.2 ; C55.1@1413,1979.99 pad.@1448.34,1992.81 ; C54.1@1447.71,1616 pad.@1448.34,1690.09 ; C57.1@1487.71,1616 pad.@1487.71,1650.72 ; pad.@1487.71,2032.18 C56.1@1492.98,2062.65 ; C50.1@1600.18,2032.18 pad.@1632.95,2032.18
  other v1: 1150.82,573.8 1131.82,634.4 1080.82,647.4 1179.82,691.4 1084,725 1174,728 1128,730 1185,764 1113,765 1148,765 1081,766
VDD: C5.1 C6.1 C7.1 C8.1 C51.1 J14.2 pad.@1672.32,2032.18 U1.K12 U3.2 U3.4 VDD.1 | length 359.8
  Top Layer w22: U1.K12@1658.76,2018.61 pad.@1672.32,2032.18
  Top Layer w25: v1(1822.52,2959.93) U3.2@1822.52,3022
  Top Layer w50: U3.2@1820.52,3021 U3.4@1820.52,3261
  Bottom Layer w20: C51.1@1665,2070 pad.@1672.32,2032.18
  other v1: 1929.52,2958.93 1775.52,2959.93 1870.7,2960.93
VDD_REG_EN: J8.35 U16.3 | length 2247.7
  Top Layer w20: U16.3@1881.9,185.21 U16.3@1882,185.21 v1(1923.1,185.21)
  INT1 w5: J8.35@335.69,957.56 285,906.87 285,729 349,665 641,665 881,425 1004,425 1249,180 1426,180 1539,293 1721,293 1828.79,185.21 v1(1923.1,185.21)
VDD_SW_EN: J8.37 U17.3 | length 2080.3
  Top Layer w20: U17.3@1881.9,371 U17.3@1882,371 v1(1923.1,371)
  INT1 w5: J8.37@335.69,857.56 395,798.25 395,725 436,684 869,684 1056,497 1056,412 1266,202 1419,202 1538,321 1587,321 1658,392 1820,392 1841,371 v1(1923.1,371)
VPPW: C1.1 C2.1 C3.1 C4.1 C52.1 pad.@1619.39,2077.17 U1.J13 U2.2 U2.4 VPPW.1 | length 363.8
  Top Layer w22: U1.J13@1619.39,2057.98 pad.@1619.39,2077.17
  Top Layer w25: v1(2712.52,2938.64) U2.2@2712.52,3000.71
  Top Layer w50: U2.2@2710.52,2999.71 U2.4@2710.52,3239.71
  Bottom Layer w20: pad.@1619.39,2077.17 C52.1@1619.39,2119.69
  other v1: 2819.52,2937.64 2665.52,2938.64 2760.7,2939.64
VWR: C9.1 C10.1 C11.1 C12.1 C53.1 pad.@1566.45,2032.18 U1.H12 U4.2 U4.4 VWR.1 | length 357.7
  Top Layer w22: pad.@1566.45,2032.18 U1.H12@1580.02,2018.61
  Top Layer w25: v1(868.52,2970.93) U4.2@868.52,3033
  Top Layer w50: U4.2@866.52,3032 U4.4@866.52,3272
  Bottom Layer w20: C53.1@1540.65,2057.98 pad.@1566.45,2032.18
  other v1: 975.52,2969.93 821.52,2970.93 916.7,2971.93
W#: pad.@1751.06,1874.7 R5.2 U1.M8 W#.1 | length 2257.8
  Top Layer w22: U1.M8@1737.5,1861.13 pad.@1751.06,1874.7
  INT1 w5: v1(2411.64,957.56) 2464.2,905 3176,905 W#.1@3277,1006
  Bottom Layer w5: pad.@1751.06,1874.7 1789.77,1836 1934,1836 2058,1712 2058,1521 2238,1341 2238,1131.2 v1(2411.64,957.56)
  Bottom Layer w20: v1(2411.64,957.56) R5.2@2446.04,957.56
W#_1: J4.36 R5.1 | length 82
  Bottom Layer w15: R5.1@2482.04,957.56 J4.36@2564.04,957.56
pads on no net: C23. C24. C25. C26. C27. C28. C29. C30. C31. C32. C33. C34. C35. C36. C37. C38. C39. C40. C41. C42. C43. C44. C45. C46. C47. C48. C49. C50. C51. C52. C53. C54. C55. C56. C57. C58.ORIGIN C60.ORIGIN C75. C76. C77.ORIGIN C78.ORIGIN C79.ORIGIN C80.ORIGIN C81. C82. C83. C84. C85. FUDICIAL1.FUDICIAL FUDICIAL2.FUDICIAL FUDICIAL3.FUDICIAL FUDICIAL4.FUDICIAL FUDICIAL5.FUDICIAL J3.3 J3.4 J3.5 J3.6 J3.7 J3.8 J3.9 J3.10 J3.13 J3.14 J3.15 J3.16 J3.17 J3.18 J3.19 J3.20 J3.23 J3.24 J3.25 J3.26 J3.27 J3.28 J3.29 J3.30 J3.36 J3.38 J3.40 J8.20 J8.26 J8.30 J8.36 J8.38 J8.39 J9. J9.2 J9.3 J14.1 L8. L9. R1. R5. R6. R7. R8. R10. R11. R12. R13. R14. R15. R16. R17. R18. R19. R20. R21. R22. R23. R24. R25. R26. R27. R28. R29. R30. R31. R32. R33. R34. R35. R36. R37. R38. R39. R40. R41. R42. R43. R44. R45. R46. R47. R48. R49. R50. R51. R52. R53. R54. R55. R56. R57. R58. R59. R60. R61. R62. R63. R64. R65. R66. R67. R68. R69. R70. R72. R77. R79. R81. R82. R83. R84. R85. R86. R87. R90. R91. R92. R93. U1. U1.GUIDEPIN_1.55_NP U1.GUIDEPIN_2.05_NP U1.H5 U1.HOLE2.3 U1.J5 U1.K5 U1.ORIGIN U5.4 U6.4 U7.4 U9. U9.3 U9.5 U10.4 U13.7 U13.12 U13.13 U14.4 U16.4 U17.4

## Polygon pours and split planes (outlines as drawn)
GND on Top Layer "NONET_L-01_P-001" (solid, remove dead copper, pour order 73): -121,3679 3379,3679 3379,-120 3371.96,-112.96 -121,-112.96
+5V_USB/(+3) on Top Layer "SMALL" (solid, remove dead copper, pour order 4): 2368,321 2391,298 2422,298 2441,279 2441,187 2451,177 2486,177 2490,181 2490,283 2511,304 2511,495 2476,530 2387,530 2368,511 2368,493
GND_EXT on Top Layer "SMALL" (solid, remove dead copper, pour order 9): 385,318 385,68 485,-32 1227,-32 1249,-10 1249,127 1090,286 943,286 812,155 697,155 579,273 579,298 458,298 428,328
VPPW on Top Layer "SMALL" (solid, remove dead copper, pour order 8): 2684,2966.71 2676,2958.71 2661,2958.71 2645,2942.71 2645,2907.71 2658,2894.71 2834,2894.71 2848,2908.71 2848,2933.71 2826,2955.71 2745,2955.71 2737,2963.71 2737,3041.71 2736,3042.71 2684,3042.71
VDD on Top Layer "SMALL" (solid, remove dead copper, pour order 7): 1794,2988 1786,2980 1771,2980 1755,2964 1755,2929 1768,2916 1944,2916 1958,2930 1958,2955 1936,2977 1855,2977 1847,2985 1847,3063 1846,3064 1794,3064
VWR on Top Layer "SMALL" (solid, remove dead copper, pour order 6): 840,2999 832,2991 817,2991 801,2975 801,2940 814,2927 990,2927 1004,2941 1004,2966 982,2988 901,2988 893,2996 893,3074 892,3075 840,3075
+5V_EXT/(+3) on Top Layer "SMALL" (solid, remove dead copper, pour order 2): 563,555 667,555 876,346 876,268 819,211 693,211 636,268 636,358 600,394 554,394 554,542 565,553
VCCQ on Top Layer "SMALL" (solid, remove dead copper, pour order 1): 1059,703 1086,730 1195,730 1212,713 1212,687 1200,675 1159,675 1149,665 1149,601 1167,583 1172,583 1172,574 1165,567 1113,567 1108,562 1074,562 1059,577
GND on Bottom Layer "NONET_L-01_P-001" (solid, remove dead copper, pour order 74): -121,-120 -121,3679 3379,3679 3379,-120
VCC_M on Bottom Layer "NONET_L-01_P-001" (solid, remove dead copper, pour order 66): 1936,642 1936,865 1959,888 1994,888 2013,907 2013,938 1994,957 1955,957 1930,932 1761,932 1736,957 1736,1114 1752,1130 2087,1130 2100,1117 2100,672 2058,630 1948,630
VCCEXT on Bottom Layer "NONET_L-01_P-001" (solid, remove dead copper, pour order 65): 1971,225 2082,225 2094,237 2094,489 2074,509 2020,509 1992,481 1992,373 1971,352
NetL6_2 on Bottom Layer "SMALL" (solid, remove dead copper, pour order 5): 2701,79 2726,54 2972,54 2985,67 2985,223 2969,239 2814,239 2803,250 2803,329 2784,348 2718,348 2701,331
+5V_EXT/(+3) on Bottom Layer "SMALL" (solid, remove dead copper, pour order 3): 603,559 662,559 870,351 870,263 816,209 695,209 650,254 650,363 634,379 604,379 570,413 570,524 598,552
VCCIO_REG on PWR1 "NONET_L-01_P-001" (solid, remove dead copper, pour order 68): -121,721.74 820.26,721.74 930,612 1417,612 1418,611 1418,232 1500,150 2146,150 2152,144 2152,-117.29 2149.29,-120 -121,-120 -121,716.72
VCC_REG on PWR1 "VPP" (solid, remove dead copper, pour order 64): 1625,800 1634,809 1856,809 2014,651 2013,650 2085,650 2225,790 2225,1039 2239,1053 3370,1053 3376,1047 3376,-114 3371,-119 2159,-119 2143,-103 2144,-103 2144,337 2026,455 1759,455 1625,589
VCC_M on PWR1 "VPP" (solid, remove dead copper, pour order 52): 2237,1054 2237,785 2095,643 2007,643 1841,809 1635,809 1627,801 1627,640 1625,612 930,612 819,723 -122,723 -120,725 -120,3681 -118,3679 2092,3679 2100,3671 2100,2496 1982,2378 921,2378 806,2263 806,1236 992,1050 2233,1050
VPPW on PWR1 "VPP" (solid, remove dead copper, pour order 49): 2406,3678 2407,3677 2407,1672 2185,1450 1305,1450 1169,1586 1169,1707 1148,1728 1148,1868 1348,2068 1347,2068 1356,2077 1549,2077 1588,2038 1669,2038 1679,2048 1680.1,2046.9 1680.1,2113.1 1740,2173 1740,2378 919,2378 806,2265 806,1232 986,1052 3380,1052 3380,3677 3378,3679 3377,3678 2407,3678
VCC on PWR1 "VPP" (solid, remove dead copper, pour order 48): 1807,1450 2186,1450 2405,1669 2405,3679 2101,3679 2101,2998 2101,2495 1984,2378 1740,2378 1740,1518 1804,1454
VCCEXT on PWR1 "NONET_L-01_P-001" (solid, remove dead copper, pour order 67): 1417,611 1418,610 1418,232 1501,149 2147,149 2152,154 2152,338 2026,464 1760,464 1612,612 1611,611 1419,611
VCC on PWR1 "VPP" (solid, remove dead copper, pour order 23): 1169,1707 1149,1727 1149,1870 1356.17,2077.17 1548.83,2077.17 1589,2037 1591,2039 1672,2039 1679,2046 1679,2111 1740,2172 1934,2172 2021,2085 2021,1588 1883,1450 1306,1450 1169,1587 1169,1704
VCCIO on PWR2 "NONET_L-01_P-001" (solid, remove dead copper, pour order 70): 3121,2692 2506,2692 2505,2693 2505,1035 2506,1034 1403,1034 1367,998 1367,647 1251,531 978,531 842,667 842,2713 769,2786 769,3672.68 762.68,3679 -121,3679 -121,-120 2014.62,-120 2014.63,-120 2014.63,183.37 1970,228 1643,228 1610,261 1608,259 1608,399 1643,434 2776,434 3123,781 3123,2693 3122,2694
VDD on PWR2 "NONET_L-01_P-001" (solid, remove dead copper, pour order 69): 1689,433 1688,434 1641,434 1610,403 1610,261 1641,230 1969,230 2013,186 2013,-117.24 2015.76,-120 3379,-120 3379,3679 1913,3679 1860,3626 1868,3618 1868,3415 1915,3368 2848,3368 3306,2910 3306,2719 3280,2693 3123,2693 3123,778 2778,433
VCCQ on PWR2 "VPP" (solid, remove dead copper, pour order 41): 841,667 976,532 1254,532 1367,645 1367,998 1402,1033 2506,1033 2506,2693 3308,2693 3308,2911 2886.5,3368.5 2480,3368.5 2166,3368.5 1969,3368.5 1969,2205 1878,2114 1779,2015 1665,2015 1654,2026 1654,2046 1647,2053 1603,2053 1600,2050 1600,2037 1586,2023 1541,2023 1454,2110 846.4,2110 841,2104.6 841,665
VDD on PWR2 "VPP" (solid, remove dead copper, pour order 31): 1600,2053 1647,2053 1653,2047 1653,2021 1659,2015 1759,2015 1970,2226 1970,3680 1669,3680 1364,3679 1364,2918 1600,2682 1600,2055 1601,2054
VWR on PWR2 "VPP" (solid, remove dead copper, pour order 30): 768,3373 768,2784 845,2707 845,2111.4 846.4,2110 1453,2110 1527,2036 1548,2017 1586,2017 1600,2031 1600,2684 1363,2921 1363,3679 1073,3679 768,3679
GND on INT1 "NONET_L-01_P-001" (solid, remove dead copper, pour order 75): 1536.63,-120 1536,86 2202,86 2286,180 2284,600 2234,647 1800,649 1694,541 1330,541 1294,577 1296,710 1361,775 1684,773 1849,939 2212,935 2373,772 2374,685 2398,658 2635,660 2802,497 2799.28,-120 3379,-120 3379,3679 -121,3679 -121,-120 1536.05,-120
VCC_M on INT1 "NONET_L-01_P-001" (solid, remove dead copper, pour order 71): 1536,86 2202,86 2284,168 2284,599 2237,646 1801,646 1695,540 1332,540 1296,576 1296,706 1363,773 1684,773 1847,936 2211,936 2372,775 2372,685 2399,658 2637,658 2799.28,495.72 2799.28,-120 1536.63,-120 1536.63,85.37
GND on GND "GND" (solid, remove dead copper, pour order 0): -121,3679 3371,3679 3371,-110 3361,-120 -121,-120 -121,3369

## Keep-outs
Keep-Out Layer:
  the board outline again, w25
